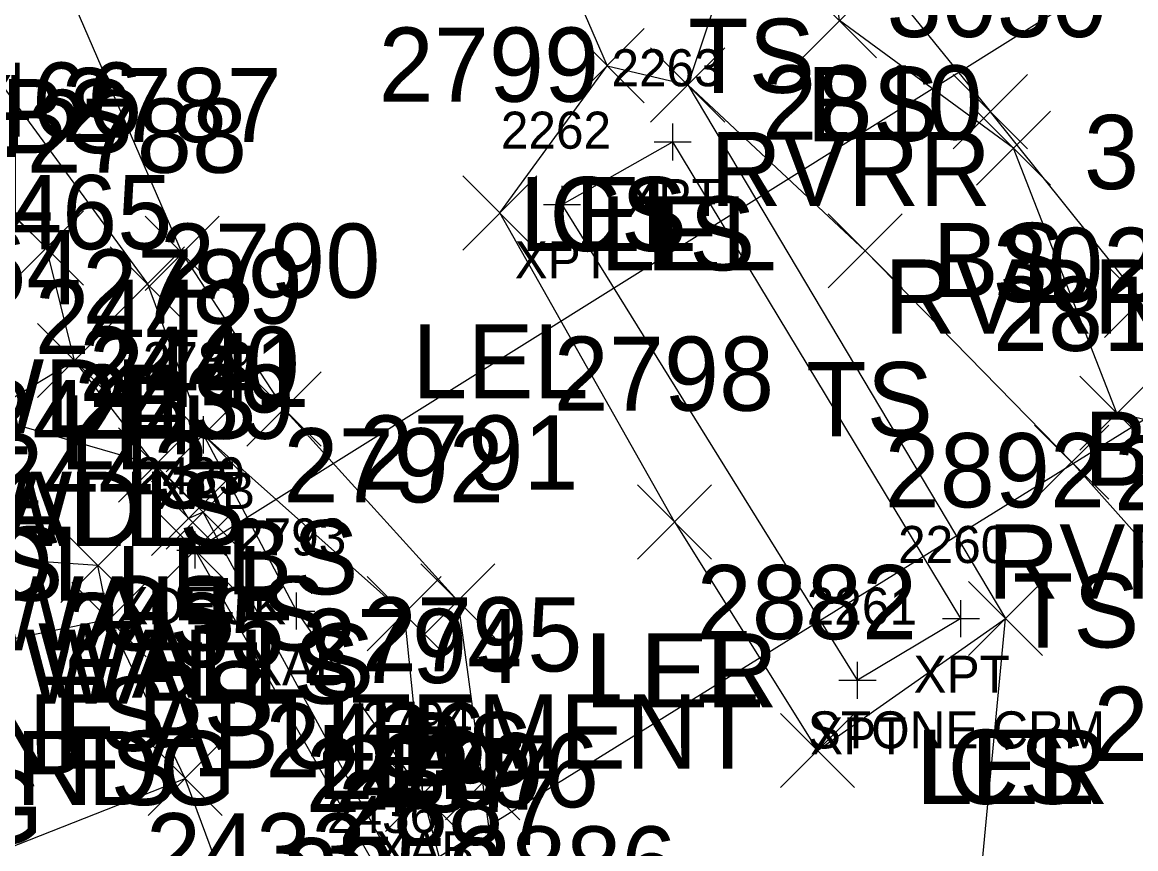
# Model space of a CAD drawing. Extents: x 1512665 to 1513714, y 110636 to 112816.
# Drawn here: x 1513039.38 to 1513069.43, y 110762.59 to 110784.88 of the extents above; entities that cross this region are included whole.
import ezdxf

# ---------------------------------------------------------------- set-up
doc = ezdxf.new("R2010")
doc.units = 0
for name, color, linetype in [('B_A', 7, 'Continuous'), ('B_C', 7, 'Continuous'), ('B_I', 7, 'Continuous'), ('B_TIC', 7, 'Continuous'), ('BELB', 7, 'Continuous'), ('BSUBM', 7, 'Continuous'), ('L_A', 7, 'Continuous'), ('L_C', 7, 'Continuous'), ('L_I', 7, 'Continuous'), ('L_TIC', 7, 'Continuous'), ('LARO', 7, 'Continuous'), ('LAWA', 7, 'Continuous'), ('LAWE', 7, 'Continuous'), ('LELB', 7, 'Continuous'), ('LWS', 7, 'Continuous'), ('P_A', 7, 'Continuous'), ('P_I', 7, 'Continuous'), ('P_TIC', 7, 'Continuous'), ('PEU', 7, 'Continuous'), ('PRC', 7, 'Continuous')]:
    doc.layers.add(name, color=color, linetype=linetype)

msp = doc.modelspace()

# ---------------------------------------------------------------- linework, layer by layer
at = {"layer": 'B_TIC'}
for p, q in [((1513056.937, 110781.65), (1513057.013, 110781.65)), ((1513056.937, 110781.65), (1513057.013, 110781.65)), ((1513053.951, 110779.967), (1513054.026, 110779.967)), ((1513044.271, 110773.75), (1513044.346, 110773.75)), ((1513044.05, 110770.643), (1513044.126, 110770.643)), ((1513046.781, 110768.997), (1513046.857, 110768.997)), ((1513064.715, 110768.793), (1513064.791, 110768.793)), ((1513064.715, 110768.793), (1513064.791, 110768.793)), ((1513061.924, 110767.13), (1513061.999, 110767.13)), ((1513050.183, 110764.057), (1513050.259, 110764.057))]:
    msp.add_line(p, q, dxfattribs=at)
for points in [[(1513056.934, 110781.15), (1513056.934, 110782.15)], [(1513056.934, 110781.15), (1513056.934, 110782.15)], [(1513056.434, 110781.65), (1513057.434, 110781.65)], [(1513056.434, 110781.65), (1513057.434, 110781.65)], [(1513053.947, 110779.467), (1513053.947, 110780.467)], [(1513053.447, 110779.967), (1513054.447, 110779.967)], [(1513044.267, 110773.25), (1513044.267, 110774.25)], [(1513043.767, 110773.75), (1513044.767, 110773.75)], [(1513044.047, 110770.143), (1513044.047, 110771.143)], [(1513043.547, 110770.643), (1513044.547, 110770.643)], [(1513046.778, 110768.497), (1513046.778, 110769.497)], [(1513064.712, 110768.293), (1513064.712, 110769.293)], [(1513064.712, 110768.293), (1513064.712, 110769.293)], [(1513046.278, 110768.997), (1513047.278, 110768.997)], [(1513064.212, 110768.793), (1513065.212, 110768.793)], [(1513064.212, 110768.793), (1513065.212, 110768.793)], [(1513061.92, 110766.63), (1513061.92, 110767.63)], [(1513061.42, 110767.13), (1513062.42, 110767.13)], [(1513050.18, 110763.557), (1513050.18, 110764.557)], [(1513049.68, 110764.057), (1513050.68, 110764.057)]]:
    msp.add_lwpolyline(points, dxfattribs=at)
at = {"layer": 'BELB'}
for points in [[(1513086.517, 110797.2), (1513044.047, 110770.643)], [(1513092.487, 110788.311), (1513049.258, 110761.513)]]:
    msp.add_lwpolyline(points, dxfattribs=at)
at = {"layer": 'BSUBM'}
for points in [[(1513064.712, 110768.793), (1513061.92, 110767.13), (1513053.947, 110779.967), (1513056.934, 110781.65)], [(1513064.712, 110768.793), (1513056.934, 110781.65)], [(1513044.267, 110773.75), (1513046.778, 110768.997), (1513050.18, 110764.057)]]:
    msp.add_lwpolyline(points, dxfattribs=at)
at = {"layer": 'L_TIC'}
for points in [[(1513060.434, 110783.922), (1513062.434, 110785.922)], [(1513062.434, 110783.922), (1513060.434, 110785.922)], [(1513054.163, 110782.705), (1513056.163, 110784.705)], [(1513056.163, 110782.705), (1513054.163, 110784.705)], [(1513054.163, 110782.705), (1513056.163, 110784.705)], [(1513056.163, 110782.705), (1513054.163, 110784.705)], [(1513056.337, 110782.187), (1513058.337, 110784.187)], [(1513058.337, 110782.187), (1513056.337, 110784.187)], [(1513056.337, 110782.187), (1513058.337, 110784.187)], [(1513058.337, 110782.187), (1513056.337, 110784.187)], [(1513064.505, 110781.466), (1513066.505, 110783.466)], [(1513066.505, 110781.466), (1513064.505, 110783.466)], [(1513065.13, 110780.48), (1513067.13, 110782.48)], [(1513067.13, 110780.48), (1513065.13, 110782.48)], [(1513051.266, 110778.735), (1513053.266, 110780.735)], [(1513053.266, 110778.735), (1513051.266, 110780.735)], [(1513039.029, 110777.791), (1513041.029, 110779.791)], [(1513041.029, 110777.791), (1513039.029, 110779.791)], [(1513042.694, 110777.644), (1513044.694, 110779.644)], [(1513044.694, 110777.644), (1513042.694, 110779.644)], [(1513061.127, 110777.714), (1513063.127, 110779.714)], [(1513063.127, 110777.714), (1513061.127, 110779.714)], [(1513041.755, 110776.819), (1513043.755, 110778.819)], [(1513043.755, 110776.819), (1513041.755, 110778.819)], [(1513068.589, 110776.378), (1513070.589, 110778.378)], [(1513070.589, 110776.378), (1513068.589, 110778.378)], [(1513039.786, 110774.756), (1513041.786, 110776.756)], [(1513041.786, 110774.756), (1513039.786, 110776.756)], [(1513039.786, 110774.756), (1513041.786, 110776.756)], [(1513041.786, 110774.756), (1513039.786, 110776.756)], [(1513045.442, 110773.448), (1513047.442, 110775.448)], [(1513047.442, 110773.448), (1513045.442, 110775.448)], [(1513067.922, 110773.334), (1513069.922, 110775.334)], [(1513069.922, 110773.334), (1513067.922, 110775.334)], [(1513043.267, 110772.75), (1513045.267, 110774.75)], [(1513045.267, 110772.75), (1513043.267, 110774.75)], [(1513041.977, 110771.935), (1513043.977, 110773.935)], [(1513043.977, 110771.935), (1513041.977, 110773.935)], [(1513041.977, 110771.935), (1513043.977, 110773.935)], [(1513043.977, 110771.935), (1513041.977, 110773.935)], [(1513066.7, 110772.015), (1513068.7, 110774.015)], [(1513068.7, 110772.015), (1513066.7, 110774.015)], [(1513043.264, 110770.665), (1513045.264, 110772.665)], [(1513045.264, 110770.665), (1513043.264, 110772.665)], [(1513042.869, 110770.497), (1513044.869, 110772.497)], [(1513044.869, 110770.497), (1513042.869, 110772.497)], [(1513055.981, 110770.4), (1513057.981, 110772.4)], [(1513057.981, 110770.4), (1513055.981, 110772.4)], [(1513055.981, 110770.4), (1513057.981, 110772.4)], [(1513057.981, 110770.4), (1513055.981, 110772.4)], [(1513043.047, 110769.643), (1513045.047, 110771.643)], [(1513045.047, 110769.643), (1513043.047, 110771.643)], [(1513040.422, 110769.227), (1513042.422, 110771.227)], [(1513042.422, 110769.227), (1513040.422, 110771.227)], [(1513050.136, 110768.273), (1513052.136, 110770.273)], [(1513052.136, 110768.273), (1513050.136, 110770.273)], [(1513048.687, 110767.929), (1513050.687, 110769.929)], [(1513050.687, 110767.929), (1513048.687, 110769.929)], [(1513040.72, 110767.766), (1513042.72, 110769.766)], [(1513042.72, 110767.766), (1513040.72, 110769.766)], [(1513064.911, 110767.796), (1513066.911, 110769.796)], [(1513066.911, 110767.796), (1513064.911, 110769.796)], [(1513064.911, 110767.796), (1513066.911, 110769.796)], [(1513066.911, 110767.796), (1513064.911, 110769.796)], [(1513064.911, 110767.796), (1513066.911, 110769.796)], [(1513066.911, 110767.796), (1513064.911, 110769.796)], [(1513059.839, 110764.239), (1513061.839, 110766.239)], [(1513061.839, 110764.239), (1513059.839, 110766.239)], [(1513050.804, 110763.37), (1513052.804, 110765.37)], [(1513052.804, 110763.37), (1513050.804, 110765.37)], [(1513049.18, 110763.057), (1513051.18, 110765.057)], [(1513051.18, 110763.057), (1513049.18, 110765.057)]]:
    msp.add_lwpolyline(points, dxfattribs=at)
at = {"layer": 'LARO'}
for points in [[(1513049.569, 110818.823), (1513041.372, 110818.074), (1513037.384, 110818.461), (1513032.798, 110807.288), (1513035.008, 110805.154), (1513035.695, 110803.452), (1513037.122, 110794.042), (1513037.836, 110784.528), (1513042.755, 110777.819), (1513044.267, 110773.75), (1513049.687, 110768.929), (1513050.18, 110764.057), (1513051.082, 110760.646), (1513051.156, 110759.692)], [(1513056.981, 110771.4), (1513052.266, 110779.735), (1513055.163, 110783.705), (1513057.337, 110783.187), (1513065.911, 110768.796)], [(1513056.981, 110771.4), (1513060.839, 110765.239), (1513065.911, 110768.796)]]:
    msp.add_lwpolyline(points, dxfattribs=at)
at = {"layer": 'LAWA'}
msp.add_lwpolyline([(1512988.199, 110800.659), (1513000.869, 110793.798), (1513013.264, 110785.095), (1513028.637, 110777.265), (1513031.778, 110776.166), (1513035.849, 110774.486), (1513038.334, 110774.274), (1513040.786, 110775.756), (1513040.029, 110778.791), (1513034.839, 110783.794), (1513031.373, 110791.45), (1513032.455, 110794.874), (1513030.687, 110802.22), (1513024.783, 110806.061), (1513019.321, 110811.594), (1513012.859, 110814.122), (1513012.233, 110818.887), (1513011.96, 110820.134), (1513029.824, 110821.619), (1513035.802, 110824.023), (1513038.307, 110832.035), (1513040.001, 110853.344)], dxfattribs=at)
at = {"layer": 'LAWE'}
msp.add_lwpolyline([(1513080.612, 110731.663), (1513081.915, 110745.763), (1513082.067, 110750.979), (1513079.314, 110751.476), (1513080.283, 110761.76), (1513080.417, 110767.703), (1513079.39, 110771.371), (1513078.326, 110772.152), (1513068.922, 110774.334), (1513066.13, 110781.48), (1513061.434, 110784.922), (1513060.4, 110792.663), (1513061.457, 110797.578)], dxfattribs=at)
at = {"layer": 'LELB'}
for points in [[(1513058.241, 110864.438), (1513056.336, 110858.446), (1513050.448, 110848.687), (1513053.381, 110841.536), (1513053.413, 110833.702), (1513052.932, 110827.898), (1513052.052, 110820.1), (1513051.896, 110813.02), (1513056.427, 110812.788), (1513056.427, 110809.608), (1513060.202, 110802.398), (1513059.911, 110795.058), (1513058.942, 110787.974), (1513057.337, 110783.187), (1513062.127, 110778.714), (1513067.7, 110773.015), (1513071.533, 110768.714), (1513070.983, 110761.956)], [(1513042.977, 110772.935), (1513038.334, 110774.274), (1513035.486, 110779.791), (1513033.224, 110783.595), (1513025.018, 110794.357), (1513010.115, 110808.489), (1513000.042, 110802.133), (1512999.104, 110815.556), (1513001.845, 110823.582), (1513003.953, 110835.587)], [(1513049.569, 110818.823), (1513048.026, 110812.296), (1513047.018, 110800.369), (1513049.597, 110796.532), (1513055.163, 110783.705)], [(1513017.973, 110817.624), (1513025.718, 110811.661), (1513032.798, 110807.288), (1513037.301, 110804.59), (1513039.457, 110802.219), (1513040.032, 110793.339), (1513040.358, 110786.347), (1513043.694, 110778.644), (1513046.442, 110774.448), (1513051.136, 110769.273), (1513051.804, 110764.37), (1513052.307, 110760.706), (1513051.156, 110759.692), (1513049.272, 110754.944), (1513048.845, 110752.609)], [(1513062.103, 110786.67), (1513065.505, 110782.466)], [(1513067.62, 110694.387), (1513071.167, 110703.267), (1513073.753, 110708.276), (1513080.884, 110709.446), (1513084.871, 110716.7), (1513089.792, 110721.227), (1513091.693, 110726.726), (1513089.103, 110729.924), (1513082.823, 110732.66), (1513082.971, 110741.966), (1513084.148, 110765.465), (1513082.534, 110771.177), (1513078.618, 110775.838), (1513069.589, 110777.378), (1513065.505, 110782.466)], [(1513041.72, 110768.766), (1513041.422, 110770.227), (1513036.074, 110770.584), (1513032.242, 110771.906)], [(1513049.258, 110761.513), (1513044.047, 110770.643)], [(1513080.582, 110729.65), (1513076.623, 110720.435), (1513071.722, 110722.319), (1513074.16, 110729.683), (1513076.706, 110735.36), (1513071.32, 110741.263), (1513073.055, 110750.837), (1513064.326, 110752.057), (1513065.911, 110768.796)]]:
    msp.add_lwpolyline(points, dxfattribs=at)
at = {"layer": 'LWS'}
msp.add_lwpolyline([(1513047.134, 110748.103), (1513047.934, 110754.951), (1513050.285, 110760.578), (1513044.264, 110771.665), (1513043.869, 110771.497), (1513042.977, 110772.935), (1513040.786, 110775.756)], dxfattribs=at)
at = {"layer": 'P_TIC'}
for points in [[(1513040.72, 110767.766), (1513042.72, 110769.766)], [(1513042.72, 110767.766), (1513040.72, 110769.766)], [(1513042.773, 110763.486), (1513044.773, 110765.486)], [(1513044.773, 110763.486), (1513042.773, 110765.486)], [(1513042.773, 110763.486), (1513044.773, 110765.486)], [(1513044.773, 110763.486), (1513042.773, 110765.486)]]:
    msp.add_lwpolyline(points, dxfattribs=at)
at = {"layer": 'PEU'}
msp.add_lwpolyline([(1512908.545, 110823.763), (1512922.462, 110816.848), (1512937.29, 110809.107), (1512956.028, 110794.571), (1512958.132, 110793.433), (1512975.798, 110779.469), (1512988.794, 110763.009), (1513002.098, 110756.133), (1513012.974, 110751.731), (1513022.336, 110752.03), (1513042.715, 110756.056), (1513045.977, 110758.546), (1513043.773, 110764.486), (1513041.72, 110768.766), (1513036.521, 110767.718), (1513024.004, 110765.991)], dxfattribs=at)
at = {"layer": 'PRC'}
msp.add_lwpolyline([(1512910.919, 110828.697), (1512924.695, 110822.052), (1512939.408, 110813.161), (1512959.787, 110799.435), (1512979.162, 110782.894), (1512994.968, 110767.907), (1513005.499, 110762.392), (1513013.716, 110758.318), (1513024.25, 110758.228), (1513034.128, 110760.688), (1513043.773, 110764.486)], dxfattribs=at)

# ---------------------------------------------------------------- texts
at = {"layer": 'B_A'}
for s, p in [('XPT', (1513055.654, 110779.65)), ('XPT', (1513055.654, 110779.65)), ('XPT', (1513052.668, 110777.967)), ('XAB', (1513042.988, 110771.75)), ('XDECK', (1513041.89, 110768.643)), ('XAB', (1513045.498, 110766.997)), ('XPT', (1513063.432, 110766.793)), ('XPT', (1513063.432, 110766.793)), ('XPT', (1513060.641, 110765.13)), ('XAB', (1513048.9, 110762.057))]:
    msp.add_text(s, height=1, dxfattribs=at).set_placement(p)
at = {"layer": 'B_C'}
msp.add_text('STONE CRM', height=1, dxfattribs=at).set_placement((1513060.578, 110765.293))
msp.add_text('STONE CRM', height=1, dxfattribs=at).set_placement((1513060.578, 110765.293))
at = {"layer": 'B_I'}
for s, p in [('2263', (1513055.28, 110783.15)), ('2263', (1513055.28, 110783.15)), ('2262', (1513052.294, 110781.467)), ('2789', (1513042.633, 110775.25)), ('2439', (1513042.413, 110772.143)), ('2793', (1513045.148, 110770.497)), ('2260', (1513063.015, 110770.293)), ('2260', (1513063.015, 110770.293)), ('2261', (1513060.55, 110768.63)), ('2794', (1513048.55, 110765.557)), ('2436', (1513047.601, 110763.013))]:
    msp.add_text(s, height=1, dxfattribs=at).set_placement(p)
at = {"layer": 'L_A'}
for s, p in [('TS', (1513057.351, 110782.974)), ('BS', (1513060.544, 110781.67)), ('BS', (1513038.799, 110781.347)), ('RVRR', (1513057.945, 110779.922)), ('LEL', (1513035.474, 110779.528)), ('LEL', (1513052.801, 110778.705)), ('CS', (1513053.604, 110778.705)), ('LEL', (1513054.975, 110778.187)), ('TS', (1513055.746, 110778.187)), ('BS', (1513063.946, 110777.466)), ('RVRR', (1513062.642, 110776.48)), ('LEL', (1513049.904, 110774.735)), ('WDL', (1513037.447, 110773.791)), ('BS', (1513042.135, 110773.644)), ('TS', (1513060.536, 110773.714)), ('LEL', (1513040.393, 110772.819)), ('BS', (1513068.03, 110772.378)), ('WALLS', (1513036.329, 110770.756)), ('WDL', (1513038.203, 110770.756)), ('BS', (1513044.883, 110769.448)), ('WDL', (1513035.752, 110769.274)), ('CS', (1513036.775, 110769.274)), ('RVRR', (1513065.433, 110769.334)), ('LEL', (1513041.905, 110768.75)), ('WALLS', (1513038.52, 110767.935)), ('CS', (1513041.418, 110767.935)), ('TS', (1513066.109, 110768.015)), ('WALLS', (1513039.413, 110766.497)), ('WALLS', (1513039.808, 110766.665)), ('LER', (1513054.564, 110766.4)), ('LEL', (1513054.619, 110766.4)), ('BS', (1513042.488, 110765.643)), ('TS', (1513039.831, 110765.227)), ('BS', (1513049.576, 110764.273)), ('TS', (1513040.129, 110763.766)), ('LEL', (1513047.325, 110763.929)), ('LER', (1513063.493, 110763.796)), ('LEL', (1513063.549, 110763.796)), ('CS', (1513064.352, 110763.796))]:
    msp.add_text(s, height=2, dxfattribs=at).set_placement(p)
at = {"layer": 'L_C'}
msp.add_text('OLD STONE ABUTEMENT', height=2, dxfattribs=at).set_placement((1513026.543, 110764.75))
at = {"layer": 'L_I'}
for s, p in [('3030', (1513062.705, 110784.48)), ('2799', (1513048.998, 110782.735)), ('2466', (1513036.667, 110781.791)), ('2787', (1513040.434, 110781.644)), ('2810', (1513059.347, 110781.714)), ('2788', (1513039.495, 110780.819)), ('3111', (1513068.03, 110780.378)), ('2465', (1513037.479, 110778.756)), ('2465', (1513037.479, 110778.756)), ('2464', (1513035.027, 110777.274)), ('2464', (1513035.027, 110777.274)), ('2790', (1513043.095, 110777.448)), ('3029', (1513065.575, 110777.334)), ('2789', (1513040.999, 110776.75)), ('2811', (1513065.574, 110776.015)), ('2442', (1513039.717, 110775.935)), ('2442', (1513039.717, 110775.935)), ('2440', (1513040.918, 110774.665)), ('2441', (1513041.177, 110774.497)), ('2798', (1513053.721, 110774.4)), ('2798', (1513053.721, 110774.4)), ('2439', (1513040.779, 110773.643)), ('2444', (1513038.162, 110773.227)), ('2791', (1513048.443, 110772.273)), ('2792', (1513046.427, 110771.929)), ('2443', (1513038.46, 110771.766)), ('2892', (1513062.651, 110771.796)), ('2892', (1513062.651, 110771.796)), ('2892', (1513062.651, 110771.796)), ('2812', (1513068.84, 110771.714)), ('2882', (1513057.579, 110768.239)), ('2795', (1513048.545, 110767.37)), ('2794', (1513046.92, 110767.057)), ('2891', (1513068.29, 110764.956)), ('2891', (1513068.29, 110764.956)), ('2436', (1513045.943, 110764.513)), ('2796', (1513048.992, 110763.706)), ('2437', (1513047.026, 110763.578)), ('2797', (1513047.822, 110763.646)), ('2887', (1513047.896, 110762.692)), ('2887', (1513047.896, 110762.692)), ('2887', (1513047.896, 110762.692)), ('2433', (1513042.717, 110761.546)), ('2886', (1513051.085, 110761.191)), ('2253', (1513046.431, 110760.875))]:
    msp.add_text(s, height=2, dxfattribs=at).set_placement(p)
at = {"layer": 'P_A'}
for p in [(1513039.208, 110763.766), (1513034.009, 110762.718)]:
    msp.add_text('RDG', height=2, dxfattribs=at).set_placement(p)
at = {"layer": 'P_I'}
for s, p in [('2443', (1513038.46, 110771.766)), ('2435', (1513040.513, 110767.486)), ('2435', (1513040.513, 110767.486)), ('2433', (1513042.717, 110761.546))]:
    msp.add_text(s, height=2, dxfattribs=at).set_placement(p)

doc.saveas('drawing.dxf')
